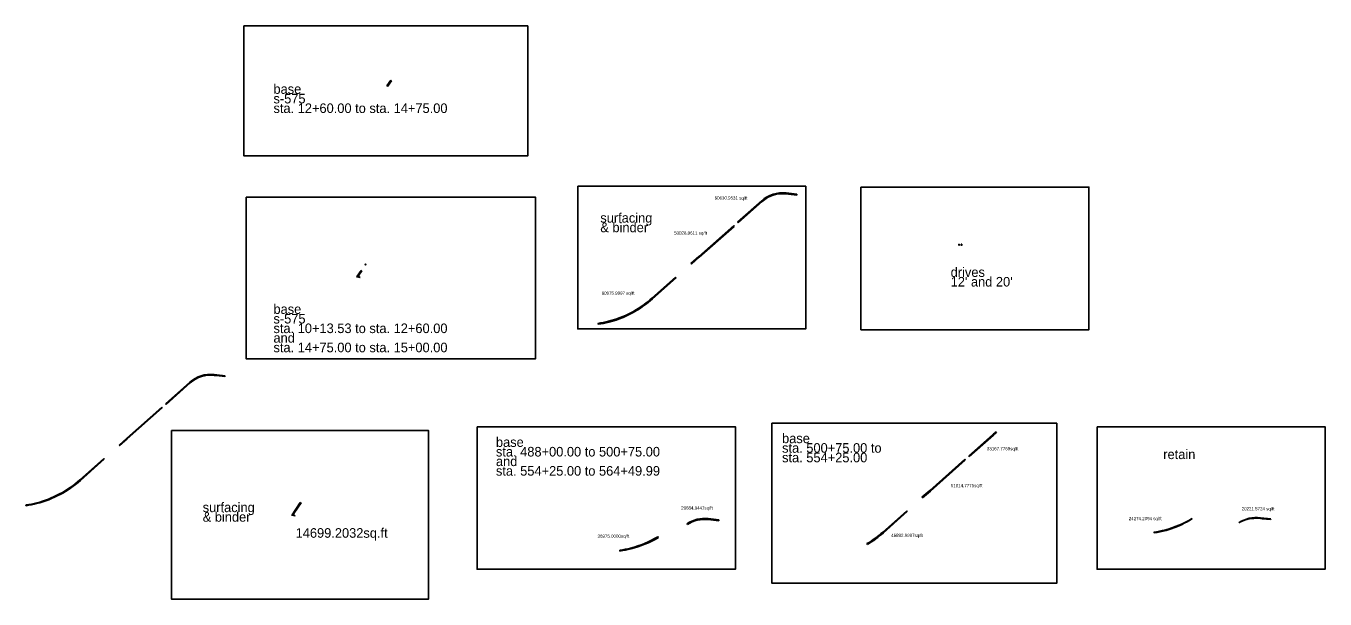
# Model space of a CAD drawing. Extents: x 51021 to 91644, y 32095 to 50030.
import ezdxf

# ---------------------------------------------------------------- set-up
doc = ezdxf.new("R2010")
doc.units = 0
for name, color, linetype in [('Level 20', 7, 'Continuous'), ('Level 26', 7, 'Continuous'), ('Level 28', 7, 'Continuous')]:
    doc.layers.add(name, color=color, linetype=linetype)

msp = doc.modelspace()

# ---------------------------------------------------------------- linework, layer by layer
at = {"layer": 'Level 20'}
for p, q in [((62305, 48154), (62426, 48332)), ((62329, 48138), (62450, 48316)), ((61374, 42198), (61499, 42382)), ((61434, 42235), (61523, 42366)), ((61619, 42560), (61633, 42581)), ((61643, 42544), (61657, 42565)), ((59341, 34734), (59599, 35118)), ((59400, 34772), (59623, 35102))]:
    msp.add_line(p, q, dxfattribs=at)
for centre, radius, start, end in [((61335, 42224), 47.5, 293.2105, 325.9793), ((61474, 42208), 47.5, 145.9793, 263.4944), ((59301, 34761), 48, 294.0858, 325.9793), ((59440, 34745), 48, 145.9793, 263.4944)]:
    msp.add_arc(centre, radius, start, end, dxfattribs=at)
at = {"layer": 'Level 26'}
for p, q in [((62305, 48154), (62329, 48138)), ((62426, 48332), (62450, 48316)), ((61499, 42382), (61523, 42366)), ((61619, 42560), (61643, 42544)), ((61633, 42581), (61657, 42565)), ((61353, 42181), (61468, 42161)), ((59599, 35118), (59623, 35102)), ((59320, 34717), (59434, 34698))]:
    msp.add_line(p, q, dxfattribs=at)
for points in [[(57835, 50030), (66710, 50030), (66710, 45962), (57835, 45962)], [(57908, 44677), (66952, 44677), (66952, 39610), (57908, 39610)], [(55570, 37365), (63613, 37365), (63613, 32095), (55570, 32095)]]:
    msp.add_lwpolyline(points, close=True, dxfattribs=at)
at = {"layer": 'Level 28'}
for p, q in [((74785, 44775), (74866, 44766)), ((74788, 44803), (75130, 44764)), ((74866, 44766), (75127, 44736)), ((75130, 44764), (75127, 44736)), ((73276, 43894), (74027, 44562)), ((73287, 43866), (74046, 44541)), ((73276, 43894), (73287, 43866)), ((72058, 42811), (73154, 43786)), ((72077, 42791), (73165, 43758)), ((73154, 43786), (73165, 43758)), ((80178, 43169), (80214, 43169)), ((80190, 43197), (80190, 43181)), ((80190, 43197), (80202, 43197)), ((80202, 43197), (80202, 43181)), ((80256, 43169), (80300, 43169)), ((80268, 43197), (80268, 43181)), ((80268, 43197), (80288, 43197)), ((80288, 43197), (80288, 43181)), ((71815, 42595), (72058, 42811)), ((71834, 42574), (72077, 42791)), ((71815, 42595), (71834, 42574)), ((70590, 41507), (71337, 42170)), ((70609, 41486), (71355, 42149)), ((71337, 42170), (71355, 42149)), ((68906, 40722), (68910, 40694)), ((56900, 39097), (56920, 39095)), ((56901, 39109), (57243, 39070)), ((56903, 39121), (57245, 39082)), ((56920, 39095), (56926, 39094)), ((56926, 39094), (56980, 39088)), ((56980, 39088), (57242, 39058)), ((57245, 39082), (57242, 39058)), ((55391, 38212), (56143, 38880)), ((55396, 38200), (56151, 38871)), ((55400, 38188), (56159, 38863)), ((55391, 38212), (55400, 38188)), ((54174, 37130), (55269, 38104)), ((54182, 37121), (55274, 38092)), ((54190, 37112), (55279, 38080)), ((55269, 38104), (55279, 38080)), ((53931, 36914), (54174, 37130)), ((53939, 36905), (54182, 37121)), ((53947, 36896), (54190, 37112)), ((80501, 36579), (81252, 37247)), ((80512, 36551), (81272, 37226)), ((81359, 37330), (81375, 37306)), ((53931, 36914), (53947, 36896)), ((80501, 36579), (80512, 36551)), ((52706, 35826), (53452, 36489)), ((52714, 35817), (53460, 36480)), ((52722, 35808), (53468, 36471)), ((53452, 36489), (53468, 36471)), ((79283, 35497), (80380, 36471)), ((79302, 35475), (80391, 36443)), ((80380, 36471), (80391, 36443)), ((79040, 35281), (79283, 35497)), ((79059, 35259), (79302, 35475)), ((51021, 35040), (51024, 35016)), ((79040, 35281), (79059, 35259)), ((72353, 34582), (72685, 34544)), ((72355, 34611), (72688, 34573)), ((72688, 34573), (72685, 34544)), ((77816, 34192), (78562, 34856)), ((77835, 34171), (78581, 34834)), ((78562, 34856), (78581, 34834)), ((87382, 34543), (87332, 34514)), ((87466, 34595), (87382, 34543)), ((87485, 34608), (87466, 34595)), ((87483, 34612), (87485, 34608)), ((88984, 34502), (89052, 34534)), ((89052, 34534), (89123, 34561)), ((89123, 34561), (89200, 34585)), ((89200, 34585), (89281, 34603)), ((89281, 34603), (89356, 34613)), ((89623, 34616), (89682, 34609)), ((89946, 34603), (89625, 34640)), ((89682, 34609), (89944, 34580)), ((89944, 34580), (89946, 34603)), ((71692, 34453), (71708, 34429)), ((86297, 34166), (86294, 34190)), ((86801, 34280), (86672, 34242)), ((86829, 34289), (86801, 34280)), ((87035, 34368), (86829, 34289)), ((87108, 34400), (87035, 34368)), ((87176, 34431), (87108, 34400)), ((87243, 34465), (87176, 34431)), ((87332, 34514), (87243, 34465)), ((88951, 34484), (88984, 34502)), ((88951, 34484), (88951, 34484)), ((70780, 34047), (70795, 34022)), ((77319, 33829), (77334, 33804)), ((69592, 33625), (69596, 33596))]:
    msp.add_line(p, q, dxfattribs=at)
for points in [[(68278, 45012), (75407, 45012), (75407, 40549), (68278, 40549)], [(77130, 44988), (84259, 44988), (84259, 40525), (77130, 40525)], [(65125, 37487), (73206, 37487), (73206, 33025), (65125, 33025)], [(74348, 37594), (83254, 37594), (83254, 32587), (74348, 32587)], [(84515, 37487), (91644, 37487), (91644, 33025), (84515, 33025)]]:
    msp.add_lwpolyline(points, close=True, dxfattribs=at)
for centre, radius, start, end in [((74678, 43830), 979, 83.4944, 131.6333), ((74678, 43830), 951, 83.4944, 131.6334), ((80178, 43181), 12, 270, 0), ((80214, 43181), 12, 180, 270), ((80256, 43181), 12, 270, 0), ((80300, 43181), 12, 180, 270), ((68425, 43944), 3260, 300.8077, 311.6332), ((68425, 43944), 3288, 300.8096, 311.6332), ((68425, 43944), 3260, 284.5125, 300.8077), ((68425, 43944), 3288, 284.5125, 300.8096), ((68527, 43547), 2851, 277.6367, 284.5124), ((68527, 43547), 2879, 277.6367, 284.5124), ((56792, 38150), 977, 83.4944, 131.6333), ((56792, 38150), 965, 83.4944, 131.6334), ((56792, 38150), 953, 83.4944, 131.6334), ((81903, 36515), 980, 123.7215, 131.6333), ((81903, 36515), 951, 123.7149, 131.6334), ((50539, 38264), 3262, 284.5125, 311.6332), ((50539, 38264), 3274, 284.5128, 311.6334), ((50539, 38264), 3286, 284.5125, 311.6332), ((50642, 37868), 2853, 277.6367, 284.5124), ((50642, 37868), 2865, 277.6367, 284.5124), ((50642, 37868), 2877, 277.6367, 284.5124), ((72238, 33627), 991, 83.2588, 123.4862), ((72239, 33625), 964, 83.2013, 123.4217), ((85812, 37413), 3262, 284.5125, 300.8077), ((89498, 33653), 995, 82.7086, 123.3942), ((89500, 33644), 979, 82.829, 98.464), ((75650, 36629), 3260, 300.8083, 311.6332), ((75650, 36629), 3289, 300.809, 311.6332), ((85915, 37017), 2853, 277.6367, 284.5124), ((85915, 37017), 2877, 277.6367, 285.2614), ((69111, 36846), 3260, 284.5125, 300.8083), ((69111, 36846), 3289, 284.5125, 300.809), ((69213, 36450), 2850, 277.6367, 284.5124), ((69213, 36450), 2879, 277.6367, 284.5124)]:
    msp.add_arc(centre, radius, start, end, dxfattribs=at)

# ---------------------------------------------------------------- texts
at = {"layer": 'Level 26'}
msp.add_text('14699.2032sq.ft', height=300, dxfattribs=at).set_placement((59453, 34013))
at = {"layer": 'Level 28'}
for s, height, p in [('base', 300, (58760, 47906)), ('s-575', 300, (58760, 47606)), ('sta. 12+60.00 to sta. 14+75.00', 300, (58760, 47306)), ('60630.9531 sq/ft', 100, (72556, 44596)), ('surfacing', 300, (68981, 43875)), ('& binder', 300, (68981, 43575)), ('50028.0611 sq/ft', 100, (71289, 43501)), ('drives', 300, (79937, 42175)), ("12' and 20'", 300, (79937, 41875)), ('80975.9997 sq/ft', 100, (69023, 41618)), ('base', 300, (58760, 41018)), ('s-575', 300, (58760, 40718)), ('sta. 10+13.53 to sta. 12+60.00', 300, (58760, 40418)), ('and', 300, (58760, 40118)), ('sta. 14+75.00 to sta. 15+00.00', 300, (58760, 39818)), ('base', 300, (65717, 36856)), ('sta. 500+75.00 to', 300, (74665, 36674)), ('base', 300, (74665, 36974)), ('sta. 488+00.00 to 500+75.00', 300, (65717, 36556)), ('and', 300, (65717, 36256)), ('sta. 554+25.00', 300, (74665, 36374)), ('33167.7769sq/ft', 100, (81069, 36750)), ('retain', 300, (86586, 36475)), ('sta. 554+25.00 to 564+49.99', 300, (65717, 35956)), ('51814.7775sq/ft', 100, (79941, 35595)), ('surfacing', 300, (56547, 34815)), ('29684.9447sq/ft', 100, (71508, 34895)), ('20221.5724 sq/ft', 100, (89036, 34871)), ('& binder', 300, (56547, 34515)), ('24274.2094 sq/ft', 100, (85505, 34563)), ('46892.9997sq/ft', 100, (78077, 34038)), ('36975.0000sq/ft', 100, (68895, 34014))]:
    msp.add_text(s, height=height, dxfattribs=at).set_placement(p)

doc.saveas('drawing.dxf')
